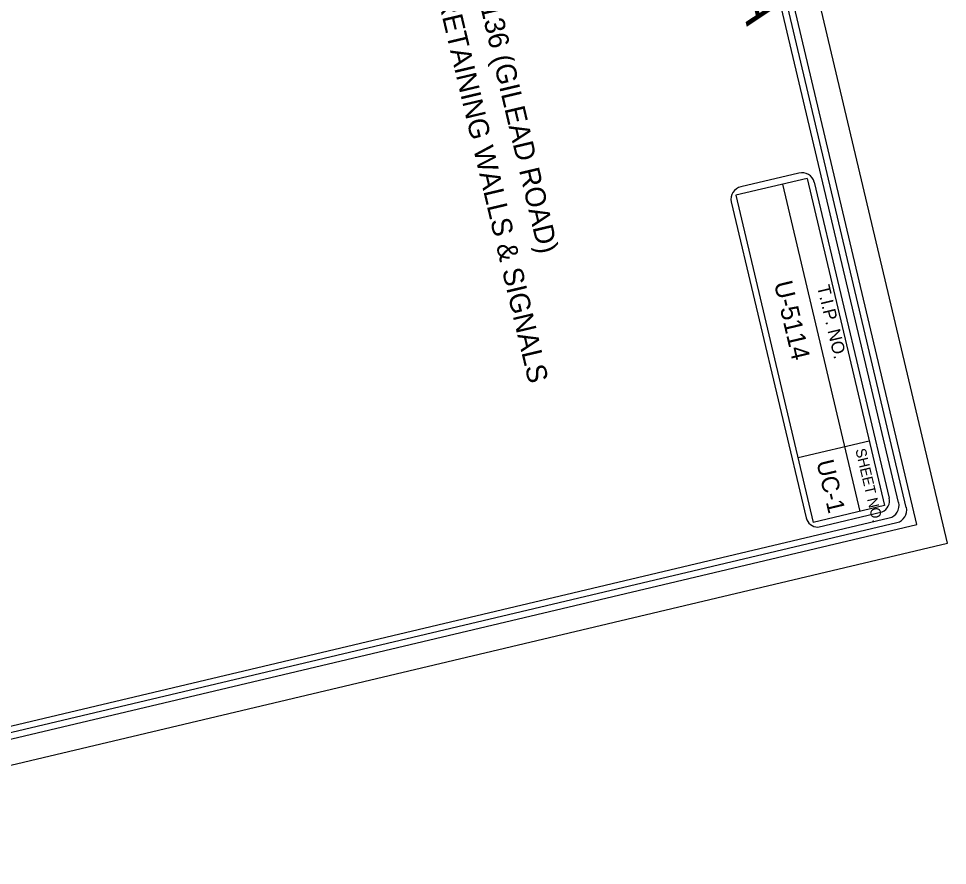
# Model space of a CAD drawing. Extents: x 1439200 to 1642353, y 394562 to 606444.
# Drawn here: x 1442416 to 1445633, y 598050 to 600981 of the extents above; entities that cross this region are included whole.
import ezdxf

# ---------------------------------------------------------------- set-up
doc = ezdxf.new("R2010")
doc.units = 0
doc.layers.add('Level 43', color=7, linetype='Continuous')
doc.layers.add('Water Line Text and Text Box and Leader Line (St)', color=7, linetype='Continuous')

msp = doc.modelspace()

# ---------------------------------------------------------------- linework, layer by layer
at = {"layer": 'Level 43'}
for p, q in [((1445118.1, 600446.2), (1444918, 600398.9)), ((1445147.1, 600428), (1444900.5, 600369.6)), ((1445147.1, 600428), (1445415.2, 599295.5)), ((1445431.8, 599321.2), (1445172.2, 600415.3)), ((1445061.8, 600407.8), (1445329.9, 599275.3)), ((1444884.4, 600347.4), (1445144, 599253.3)), ((1444900.5, 600369.6), (1445168.5, 599237.1)), ((1445362.3, 599518.9), (1445115.7, 599460.6)), ((1445415.2, 599295.5), (1445168.5, 599237.1))]:
    msp.add_line(p, q, dxfattribs=at)
msp.add_lwpolyline([(1445632.9, 599164.9), (1443909.8, 606443.8), (1439200, 605328.8), (1440923.1, 598050)], close=True, dxfattribs=at)
for points in [[(1445490.4, 599289.4), (1443990.3, 605626.4)], [(1445463.9, 599305.8), (1444024.6, 605385.7)], [(1441856, 598406.5), (1445431.2, 599252.8)], [(1445184.6, 599220.8), (1445406.7, 599273.4)], [(1441047.6, 598192.5), (1445457.7, 599236.5)]]:
    msp.add_lwpolyline(points, dxfattribs=at)
for centre in [(1445421.3, 599295.7), (1445447.8, 599279.3)]:
    msp.add_arc(centre, 44, 283.3181, 13.3181, dxfattribs=at)
for centre, major_axis, ratio, start_param, end_param in [((1445128.1, 600405), (43.9, 10.4), 0.941469, 0.000468, 1.571265), ((1444928.1, 600357.5), (-43.9, -10.4), 0.941469, 4.712857, 6.283654), ((1445387.7, 599310.8), (43.9, 10.4), 0.926296, 4.933032, 6.283554), ((1445187.7, 599263.4), (-43.9, -10.4), 0.941469, 0.000472, 1.282481)]:
    msp.add_ellipse(centre, major_axis=major_axis, ratio=ratio, start_param=start_param, end_param=end_param, dxfattribs=at)
at = {"layer": 'Water Line Text and Text Box and Leader Line (St)'}
msp.add_lwpolyline([(1439298.8, 605293.4), (1440988.4, 598155.9), (1445527, 599230.3), (1443837.3, 606367.8)], close=True, dxfattribs=at)

# ---------------------------------------------------------------- texts
at = {"layer": 'Level 43'}
for s, height, rotation, p in [('STATE OF NORTH CAROLINA', 135.18, 283.3466, (1444349.2, 603434.4)), ('TYPE OF WORK: GRADING, PAVING, DRAINAGE, RETAINING WALLS & SIGNALS', 70.155, 283.3038, (1443358.5, 603204.5)), ('LOCATION: US-21 (STATESVILLE ROAD) AND SR 2136 (GILEAD ROAD)', 70.155, 283.3038, (1443493.9, 603227)), ('U-5114', 63.64, 283.3466, (1445031.8, 600065.5)), ('T.I.P. NO.', 43.92, 283.3466, (1445181.2, 600053.6)), ('SHEET NO.', 36.29, 283.3466, (1445313.9, 599488.8)), ('UC-1', 59.89, 283.3466, (1445178.7, 599446.7))]:
    msp.add_text(s, height=height, rotation=rotation, dxfattribs=at).set_placement(p)

doc.saveas('drawing.dxf')
